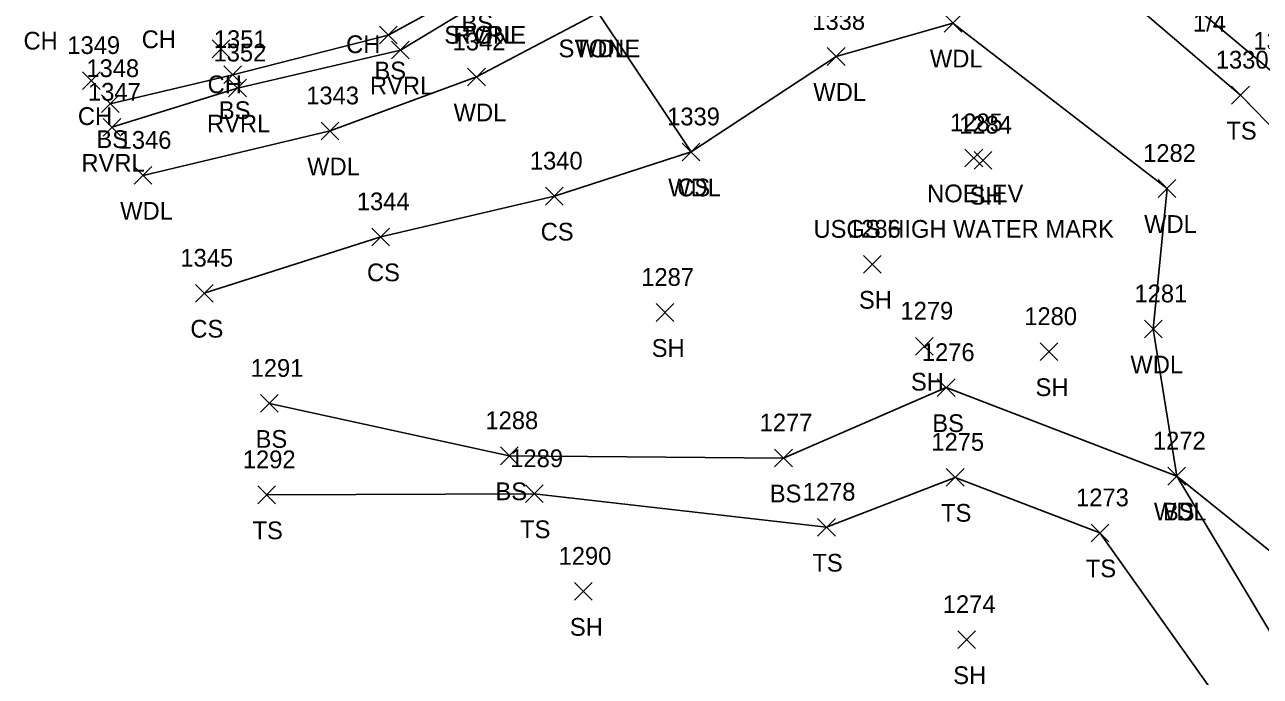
# Model space of a CAD drawing. Extents: x 1537342 to 1542195, y 163002 to 168596.
# Drawn here: x 1541687.7 to 1541827.1, y 163200.7 to 163274.1 of the extents above; entities that cross this region are included whole.
import ezdxf

# ---------------------------------------------------------------- set-up
doc = ezdxf.new("R2010")
doc.units = 0
for name, color, linetype in [('L_A', 7, 'Continuous'), ('L_I', 7, 'Continuous'), ('L_TIC', 7, 'Continuous'), ('LAWA', 7, 'Continuous'), ('LAWE', 7, 'Continuous'), ('LELB', 7, 'Continuous'), ('M_A', 7, 'Continuous'), ('M_C', 7, 'Continuous'), ('M_I', 7, 'Continuous'), ('M_TIC', 7, 'Continuous'), ('U_C', 7, 'Continuous')]:
    doc.layers.add(name, color=color, linetype=linetype)

msp = doc.modelspace()

# ---------------------------------------------------------------- linework, layer by layer
at = {"layer": 'L_TIC'}
for points in [[(1541791.4, 163273.28), (1541793.4, 163275.28)], [(1541793.4, 163273.28), (1541791.4, 163275.28)], [(1541727.73, 163271.94), (1541729.73, 163273.94)], [(1541729.73, 163271.94), (1541727.73, 163273.94)], [(1541708.87, 163270.38), (1541710.87, 163272.38)], [(1541710.87, 163270.38), (1541708.87, 163272.38)], [(1541729.1, 163270.24), (1541731.1, 163272.24)], [(1541731.1, 163270.24), (1541729.1, 163272.24)], [(1541778.24, 163269.52), (1541780.24, 163271.52)], [(1541780.24, 163269.52), (1541778.24, 163271.52)], [(1541710.19, 163267.47), (1541712.19, 163269.47)], [(1541712.19, 163267.47), (1541710.19, 163269.47)], [(1541694.24, 163266.8), (1541696.24, 163268.8)], [(1541696.24, 163266.8), (1541694.24, 163268.8)], [(1541737.68, 163267.21), (1541739.68, 163269.21)], [(1541739.68, 163267.21), (1541737.68, 163269.21)], [(1541710.73, 163265.96), (1541712.73, 163267.96)], [(1541712.73, 163265.96), (1541710.73, 163267.96)], [(1541823.83, 163265.16), (1541825.83, 163267.16)], [(1541825.83, 163265.16), (1541823.83, 163267.16)], [(1541696.38, 163264.2), (1541698.38, 163266.2)], [(1541698.38, 163264.2), (1541696.38, 163266.2)], [(1541696.57, 163261.54), (1541698.57, 163263.54)], [(1541698.57, 163261.54), (1541696.57, 163263.54)], [(1541721.17, 163261.13), (1541723.17, 163263.13)], [(1541723.17, 163261.13), (1541721.17, 163263.13)], [(1541761.88, 163258.76), (1541763.88, 163260.76)], [(1541763.88, 163258.76), (1541761.88, 163260.76)], [(1541761.88, 163258.76), (1541763.88, 163260.76)], [(1541763.88, 163258.76), (1541761.88, 163260.76)], [(1541794.8, 163257.83), (1541796.8, 163259.83)], [(1541796.8, 163257.83), (1541794.8, 163259.83)], [(1541700.08, 163256.12), (1541702.08, 163258.12)], [(1541702.08, 163256.12), (1541700.08, 163258.12)], [(1541746.47, 163253.78), (1541748.47, 163255.78)], [(1541748.47, 163253.78), (1541746.47, 163255.78)], [(1541815.56, 163254.64), (1541817.56, 163256.64)], [(1541817.56, 163254.64), (1541815.56, 163256.64)], [(1541726.88, 163249.19), (1541728.88, 163251.19)], [(1541728.88, 163249.19), (1541726.88, 163251.19)], [(1541782.32, 163246.1), (1541784.32, 163248.1)], [(1541784.32, 163246.1), (1541782.32, 163248.1)], [(1541706.98, 163242.84), (1541708.98, 163244.84)], [(1541708.98, 163242.84), (1541706.98, 163244.84)], [(1541758.95, 163240.67), (1541760.95, 163242.67)], [(1541760.95, 163240.67), (1541758.95, 163242.67)], [(1541814, 163238.81), (1541816, 163240.81)], [(1541816, 163238.81), (1541814, 163240.81)], [(1541788.19, 163236.87), (1541790.19, 163238.87)], [(1541790.19, 163236.87), (1541788.19, 163238.87)], [(1541802.23, 163236.25), (1541804.23, 163238.25)], [(1541804.23, 163236.25), (1541802.23, 163238.25)], [(1541790.64, 163232.2), (1541792.64, 163234.2)], [(1541792.64, 163232.2), (1541790.64, 163234.2)], [(1541714.33, 163230.42), (1541716.33, 163232.42)], [(1541716.33, 163230.42), (1541714.33, 163232.42)], [(1541741.38, 163224.52), (1541743.38, 163226.52)], [(1541743.38, 163224.52), (1541741.38, 163226.52)], [(1541772.3, 163224.27), (1541774.3, 163226.27)], [(1541774.3, 163224.27), (1541772.3, 163226.27)], [(1541791.66, 163222.09), (1541793.66, 163224.09)], [(1541793.66, 163222.09), (1541791.66, 163224.09)], [(1541816.65, 163222.23), (1541818.65, 163224.23)], [(1541818.65, 163222.23), (1541816.65, 163224.23)], [(1541816.65, 163222.23), (1541818.65, 163224.23)], [(1541818.65, 163222.23), (1541816.65, 163224.23)], [(1541714.02, 163220.12), (1541716.02, 163222.12)], [(1541716.02, 163220.12), (1541714.02, 163222.12)], [(1541744.19, 163220.24), (1541746.19, 163222.24)], [(1541746.19, 163220.24), (1541744.19, 163222.24)], [(1541777.15, 163216.47), (1541779.15, 163218.47)], [(1541779.15, 163216.47), (1541777.15, 163218.47)], [(1541807.98, 163215.83), (1541809.98, 163217.83)], [(1541809.98, 163215.83), (1541807.98, 163217.83)], [(1541749.72, 163209.24), (1541751.72, 163211.24)], [(1541751.72, 163209.24), (1541749.72, 163211.24)], [(1541792.96, 163203.8), (1541794.96, 163205.8)], [(1541794.96, 163203.8), (1541792.96, 163205.8)]]:
    msp.add_lwpolyline(points, dxfattribs=at)
at = {"layer": 'LAWA'}
msp.add_lwpolyline([(1541844.86, 163168.93), (1541849.55, 163183.81), (1541839.11, 163205.97), (1541817.65, 163223.23), (1541815, 163239.81), (1541816.56, 163255.64), (1541792.4, 163274.28), (1541779.24, 163270.52), (1541762.88, 163259.76), (1541752.39, 163275.43), (1541738.68, 163268.21), (1541722.17, 163262.13), (1541701.08, 163257.12)], dxfattribs=at)
at = {"layer": 'LAWE'}
msp.add_lwpolyline([(1541697.57, 163262.54), (1541711.73, 163266.96), (1541730.1, 163271.24), (1541739.51, 163276.96), (1541746.47, 163282.88), (1541755.03, 163290.89), (1541767.29, 163298.26), (1541776.81, 163302.23), (1541780.9, 163305.15), (1541791.03, 163307.2)], dxfattribs=at)
at = {"layer": 'LELB'}
for points in [[(1541697.38, 163265.2), (1541711.19, 163268.47), (1541728.73, 163272.94), (1541738.54, 163278.3), (1541744.94, 163284.53), (1541750.45, 163291.78), (1541762.36, 163297.06), (1541764.63, 163298.71), (1541768.94, 163301.66), (1541775.91, 163303.98), (1541780.38, 163306.77), (1541791.08, 163308.95)], [(1541920.52, 163124.04), (1541935.16, 163148.54), (1541933.92, 163173.02), (1541915.6, 163197.94), (1541891.22, 163224.52), (1541851.87, 163246.31), (1541828.99, 163268.29), (1541806.16, 163287.41), (1541789.02, 163298.58), (1541787.18, 163300.8)], [(1541912.53, 163131.42), (1541929, 163149.96), (1541922.93, 163163.15), (1541906.57, 163185.36), (1541883.88, 163218.47), (1541847.29, 163243.18), (1541824.83, 163266.16), (1541803.8, 163284.14), (1541786.25, 163296.89)], [(1541762.88, 163259.76), (1541747.47, 163254.78), (1541727.88, 163250.19), (1541707.98, 163243.84)], [(1541844.86, 163168.93), (1541831.91, 163199.44), (1541817.65, 163223.23), (1541791.64, 163233.2), (1541773.3, 163225.27), (1541742.38, 163225.52), (1541715.33, 163231.42)], [(1541833.08, 163165.43), (1541825.57, 163193.47), (1541808.98, 163216.83), (1541792.66, 163223.09), (1541778.15, 163217.47), (1541745.19, 163221.24), (1541715.02, 163221.12)]]:
    msp.add_lwpolyline(points, dxfattribs=at)
at = {"layer": 'M_TIC'}
for points in [[(1541793.76, 163258.09), (1541795.76, 163260.09)], [(1541795.76, 163258.09), (1541793.76, 163260.09)]]:
    msp.add_lwpolyline(points, dxfattribs=at)

# ---------------------------------------------------------------- texts
at = {"layer": 'L_A'}
for s, p in [('BS', (1541736.98, 163273.3)), ('STONE', (1541735.05, 163271.96)), ('RVRL', (1541736.08, 163271.96)), ('CH', (1541687.6, 163271.3)), ('CH', (1541700.93, 163271.46)), ('CH', (1541723.98, 163270.9)), ('STONE', (1541747.93, 163270.43)), ('WDL', (1541749.8, 163270.43)), ('WDL', (1541789.81, 163269.28)), ('BS', (1541727.17, 163267.94)), ('CH', (1541708.36, 163266.38)), ('RVRL', (1541726.67, 163266.24)), ('WDL', (1541776.66, 163265.52)), ('BS', (1541709.63, 163263.47)), ('CH', (1541693.73, 163262.8)), ('RVRL', (1541708.29, 163261.96)), ('WDL', (1541736.1, 163263.21)), ('TS', (1541823.24, 163261.16)), ('BS', (1541695.82, 163260.2)), ('RVRL', (1541694.13, 163257.54)), ('WDL', (1541719.59, 163257.13)), ('WDL', (1541760.3, 163254.76)), ('CS', (1541761.32, 163254.76)), ('SH', (1541794.29, 163253.83)), ('WDL', (1541698.5, 163252.12)), ('CS', (1541745.92, 163249.78)), ('WDL', (1541813.97, 163250.64)), ('CS', (1541726.33, 163245.19)), ('SH', (1541781.81, 163242.1)), ('CS', (1541706.42, 163238.84)), ('SH', (1541758.44, 163236.67)), ('WDL', (1541812.42, 163234.81)), ('SH', (1541787.67, 163232.87)), ('SH', (1541801.72, 163232.25)), ('BS', (1541790.08, 163228.2)), ('BS', (1541713.77, 163226.42)), ('BS', (1541740.82, 163220.52)), ('BS', (1541771.75, 163220.27)), ('TS', (1541791.07, 163218.09)), ('WDL', (1541815.07, 163218.23)), ('BS', (1541816.09, 163218.23)), ('TS', (1541713.43, 163216.12)), ('TS', (1541743.6, 163216.24)), ('TS', (1541776.56, 163212.47)), ('TS', (1541807.39, 163211.83)), ('SH', (1541749.21, 163205.24)), ('SH', (1541792.44, 163199.8))]:
    msp.add_text(s, height=2, dxfattribs=at).set_placement(p)
at = {"layer": 'L_I'}
for s, p in [('1338', (1541776.55, 163273.52)), ('1349', (1541692.54, 163270.8)), ('1351', (1541709.06, 163271.47)), ('1342', (1541735.99, 163271.21)), ('1329', (1541826.29, 163271.29)), ('1352', (1541709.03, 163269.96)), ('1330', (1541822.05, 163269.16)), ('1348', (1541694.69, 163268.2)), ('1347', (1541694.87, 163265.54)), ('1343', (1541719.48, 163265.13)), ('1339', (1541760.18, 163262.76)), ('1339', (1541760.18, 163262.76)), ('1284', (1541793.11, 163261.83)), ('1346', (1541698.33, 163260.12)), ('1340', (1541744.7, 163257.78)), ('1282', (1541813.86, 163258.64)), ('1344', (1541725.19, 163253.19)), ('1286', (1541780.57, 163250.1)), ('1345', (1541705.29, 163246.84)), ('1287', (1541757.26, 163244.67)), ('1281', (1541812.88, 163242.81)), ('1279', (1541786.49, 163240.87)), ('1280', (1541800.45, 163240.25)), ('1276', (1541788.9, 163236.2)), ('1291', (1541713.21, 163234.42)), ('1288', (1541739.69, 163228.52)), ('1277', (1541770.61, 163228.27)), ('1275', (1541789.97, 163226.09)), ('1272', (1541814.96, 163226.23)), ('1272', (1541814.96, 163226.23)), ('1289', (1541742.49, 163224.24)), ('1292', (1541712.33, 163224.12)), ('1278', (1541775.46, 163220.47)), ('1273', (1541806.29, 163219.83)), ('1290', (1541747.94, 163213.24)), ('1274', (1541791.26, 163207.8))]:
    msp.add_text(s, height=2, dxfattribs=at).set_placement(p)
at = {"layer": 'M_A'}
msp.add_text('NOELEV', height=2, dxfattribs=at).set_placement((1541789.5, 163254.09))
at = {"layer": 'M_C'}
msp.add_text('USGS HIGH WATER MARK', height=2, dxfattribs=at).set_placement((1541776.68, 163250.09))
at = {"layer": 'M_I'}
msp.add_text('1285', height=2, dxfattribs=at).set_placement((1541792.07, 163262.09))
at = {"layer": 'U_C'}
msp.add_text('1/4', height=2, dxfattribs=at).set_placement((1541819.47, 163273.33))

doc.saveas('drawing.dxf')
